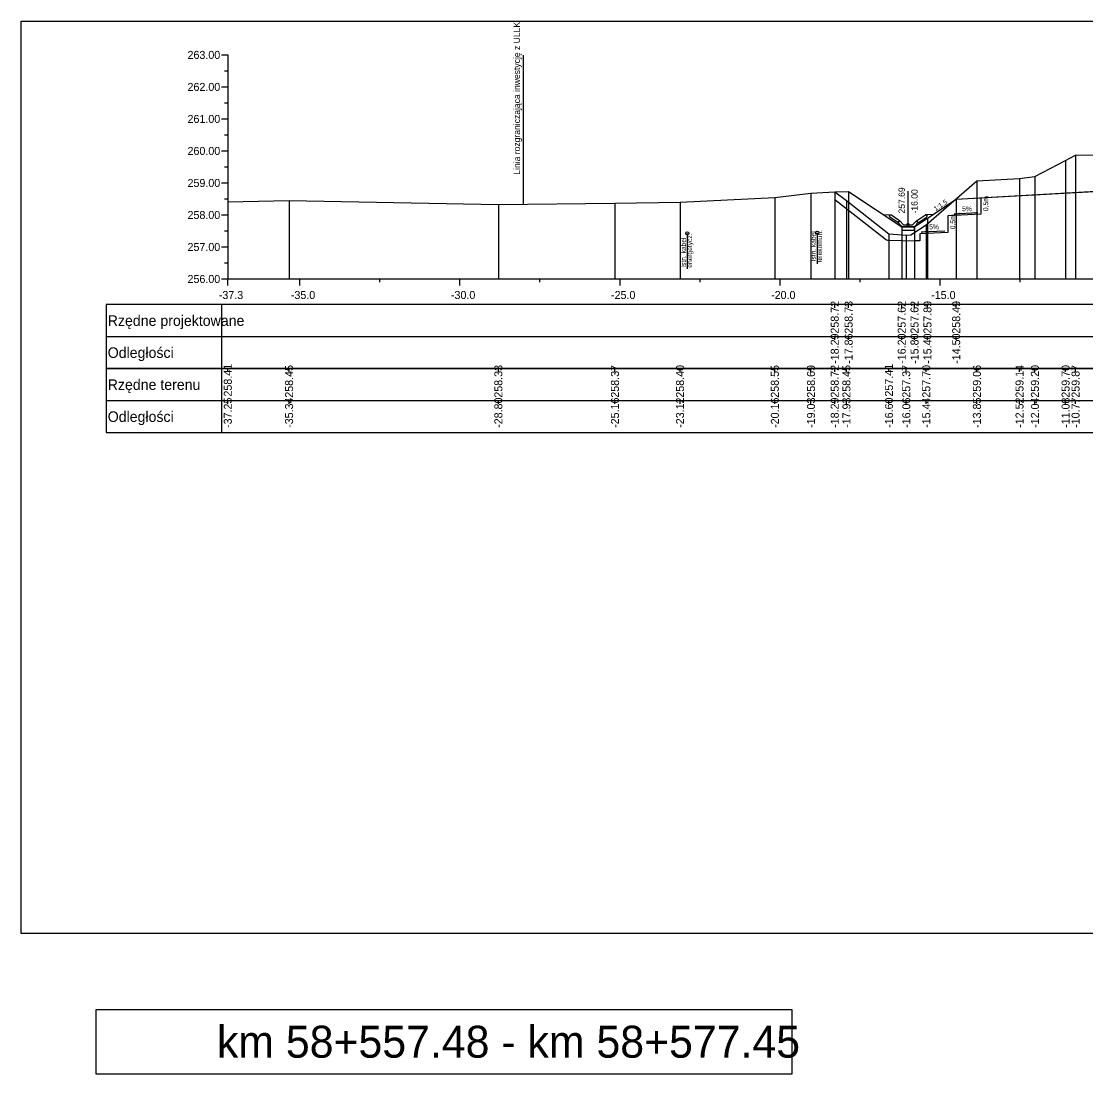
# Model space of a CAD drawing. Extents: x 6516023 to 6560129, y 5513077 to 5529206.
# Drawn here: x 6516634.51 to 6516667.76, y 5514513.78 to 5514546.66 of the extents above; entities that cross this region are included whole.
import ezdxf

# ---------------------------------------------------------------- set-up
doc = ezdxf.new("R2010")
doc.units = 0
for name, color, linetype in [('IR_default', 7, 'Continuous'), ('TOR_PRZEK_P-kable', 7, 'Continuous'), ('TOR_PRZEK_P-odwodnienie', 7, 'Continuous'), ('TOR_PRZEK_P-opisy', 7, 'Continuous'), ('TOR_PRZEK_P-pomoc', 7, 'Continuous'), ('TOR_PRZEK_P-schodkowanie+wymiana', 7, 'Continuous'), ('TOR_PRZEK_P-tabelka istniejace', 7, 'Continuous'), ('TOR_PRZEK_P-tabelka projektowane', 7, 'Continuous'), ('TOR_PRZEK_P-teren istniejacy', 7, 'Continuous'), ('TOR_PRZEK_P-uklad odniesienia', 7, 'Continuous'), ('TOR_PRZEK_P-warstwa ochronna II', 7, 'Continuous'), ('TOR_PS_T-granica PKP-projektowana', 7, 'Continuous'), ('TOR_PS_T-skarpy projektowane', 7, 'Continuous'), ('TOR_RAMKI-ramka+tabelka 1', 7, 'Continuous')]:
    doc.layers.add(name, color=color, linetype=linetype)

msp = doc.modelspace()

# ---------------------------------------------------------------- linework, layer by layer
at = {"layer": 'IR_default'}
msp.add_lwpolyline([(6516659.919, 5514541.328), (6516660.353, 5514541.336), (6516662.012, 5514540.231), (6516662.104, 5514540.231), (6516662.412, 5514540.231), (6516662.505, 5514540.293), (6516662.817, 5514540.501), (6516663.025, 5514540.64), (6516663.713, 5514541.098), (6516668.018, 5514541.344)], dxfattribs=at)
at = {"layer": 'TOR_PRZEK_P-kable'}
for p, q in [((6516655.315, 5514540.031), (6516655.315, 5514538.921)), ((6516659.373, 5514540.05), (6516659.373, 5514539.076))]:
    msp.add_line(p, q, dxfattribs=at)
for centre in [(6516655.315, 5514540.031), (6516659.373, 5514540.05)]:
    msp.add_circle(centre, 0.05, dxfattribs=at)
at = {"layer": 'TOR_PRZEK_P-odwodnienie'}
for p, q in [((6516662.212, 5514540.301), (6516662.212, 5514541.345)), ((6516661.903, 5514540.36), (6516661.641, 5514540.534)), ((6516661.947, 5514540.426), (6516661.667, 5514540.613)), ((6516662.476, 5514540.426), (6516662.757, 5514540.613)), ((6516662.521, 5514540.36), (6516662.782, 5514540.534)), ((6516661.914, 5514540.377), (6516661.903, 5514540.36)), ((6516661.904, 5514540.396), (6516661.952, 5514540.42)), ((6516661.947, 5514540.426), (6516661.939, 5514540.414)), ((6516662.072, 5514540.301), (6516661.952, 5514540.42)), ((6516662.022, 5514540.231), (6516662.402, 5514540.231)), ((6516662.072, 5514540.301), (6516662.352, 5514540.301)), ((6516662.352, 5514540.301), (6516662.472, 5514540.42)), ((6516662.472, 5514540.42), (6516662.519, 5514540.396)), ((6516662.476, 5514540.426), (6516662.485, 5514540.414)), ((6516662.51, 5514540.377), (6516662.521, 5514540.36))]:
    msp.add_line(p, q, dxfattribs=at)
for points in [[(6516661.42, 5514540.625), (6516661.667, 5514540.613)], [(6516661.617, 5514540.587), (6516661.667, 5514540.613)], [(6516661.617, 5514540.587), (6516661.641, 5514540.534)], [(6516663.003, 5514540.625), (6516662.757, 5514540.613)], [(6516662.807, 5514540.587), (6516662.757, 5514540.613)], [(6516662.807, 5514540.587), (6516662.782, 5514540.534)], [(6516661.939, 5514540.414), (6516661.904, 5514540.395)], [(6516661.952, 5514540.301), (6516661.904, 5514540.396)], [(6516661.904, 5514540.395), (6516661.914, 5514540.377)], [(6516662.022, 5514540.231), (6516661.952, 5514540.301)], [(6516662.012, 5514540.231), (6516662.011, 5514540.231), (6516662.012, 5514540.231), (6516662.011, 5514540.23), (6516662.012, 5514540.231), (6516662.012, 5514540.23), (6516662.012, 5514540.231), (6516662.012, 5514540.231)], [(6516662.412, 5514540.231), (6516662.012, 5514540.231), (6516662.012, 5514540.131), (6516662.412, 5514540.131), (6516662.412, 5514540.231)], [(6516662.402, 5514540.231), (6516662.472, 5514540.301)], [(6516662.412, 5514540.231), (6516662.411, 5514540.231), (6516662.412, 5514540.231), (6516662.411, 5514540.23), (6516662.412, 5514540.231), (6516662.412, 5514540.23), (6516662.412, 5514540.231), (6516662.412, 5514540.231)], [(6516662.472, 5514540.301), (6516662.519, 5514540.396)], [(6516662.485, 5514540.414), (6516662.52, 5514540.395)], [(6516662.52, 5514540.395), (6516662.51, 5514540.377)]]:
    msp.add_lwpolyline(points, dxfattribs=at)
msp.add_circle((6516662.212, 5514540.301), 0.035, dxfattribs=at)
at = {"layer": 'TOR_PRZEK_P-pomoc'}
msp.add_lwpolyline([(6516658.587, 5514515.781), (6516636.837, 5514515.781), (6516636.837, 5514513.781), (6516658.587, 5514513.781)], close=True, dxfattribs=at)
at = {"layer": 'TOR_PRZEK_P-schodkowanie+wymiana'}
for p, q in [((6516664.479, 5514541.142), (6516664.479, 5514540.627)), ((6516664.479, 5514540.627), (6516663.449, 5514540.576)), ((6516663.449, 5514540.576), (6516663.449, 5514540.061)), ((6516661.598, 5514539.815), (6516662.412, 5514539.798))]:
    msp.add_line(p, q, dxfattribs=at)
for points in [[(6516659.919, 5514541.086), (6516661.49, 5514539.857)], [(6516663.449, 5514540.061), (6516662.573, 5514540.017), (6516662.573, 5514539.798), (6516662.412, 5514539.798)]]:
    msp.add_lwpolyline(points, dxfattribs=at)
msp.add_arc((6516661.613, 5514540.014), 0.2, 231.9586, 265.5776, dxfattribs=at)
at = {"layer": 'TOR_PRZEK_P-tabelka istniejace'}
for p, q in [((6516637.163, 5514535.806), (6516637.163, 5514533.806)), ((6516640.763, 5514535.806), (6516640.763, 5514533.806)), ((6516640.963, 5514535.706), (6516640.963, 5514535.806)), ((6516642.877, 5514535.706), (6516642.877, 5514535.806)), ((6516649.414, 5514535.706), (6516649.414, 5514535.806)), ((6516653.055, 5514535.706), (6516653.055, 5514535.806)), ((6516655.088, 5514535.706), (6516655.088, 5514535.806)), ((6516658.049, 5514535.706), (6516658.049, 5514535.806)), ((6516659.178, 5514535.706), (6516659.178, 5514535.806)), ((6516659.919, 5514535.706), (6516659.919, 5514535.806)), ((6516660.285, 5514535.706), (6516660.285, 5514535.806)), ((6516661.613, 5514535.706), (6516661.613, 5514535.806)), ((6516662.155, 5514535.706), (6516662.155, 5514535.806)), ((6516662.778, 5514535.706), (6516662.778, 5514535.806)), ((6516664.36, 5514535.706), (6516664.36, 5514535.806)), ((6516665.691, 5514535.706), (6516665.691, 5514535.806)), ((6516666.172, 5514535.706), (6516666.172, 5514535.806)), ((6516667.13, 5514535.706), (6516667.13, 5514535.806)), ((6516667.442, 5514535.706), (6516667.442, 5514535.806)), ((6516637.163, 5514534.806), (6516720.963, 5514534.806)), ((6516640.963, 5514534.706), (6516640.963, 5514534.806)), ((6516642.877, 5514534.706), (6516642.877, 5514534.806)), ((6516649.414, 5514534.706), (6516649.414, 5514534.806)), ((6516653.055, 5514534.706), (6516653.055, 5514534.806)), ((6516655.088, 5514534.706), (6516655.088, 5514534.806)), ((6516658.049, 5514534.706), (6516658.049, 5514534.806)), ((6516659.178, 5514534.706), (6516659.178, 5514534.806)), ((6516659.919, 5514534.706), (6516659.919, 5514534.806)), ((6516660.285, 5514534.706), (6516660.285, 5514534.806)), ((6516661.613, 5514534.706), (6516661.613, 5514534.806)), ((6516662.155, 5514534.706), (6516662.155, 5514534.806)), ((6516662.778, 5514534.706), (6516662.778, 5514534.806)), ((6516664.36, 5514534.706), (6516664.36, 5514534.806)), ((6516665.691, 5514534.706), (6516665.691, 5514534.806)), ((6516666.172, 5514534.706), (6516666.172, 5514534.806)), ((6516667.13, 5514534.706), (6516667.13, 5514534.806)), ((6516667.442, 5514534.706), (6516667.442, 5514534.806))]:
    msp.add_line(p, q, dxfattribs=at)
for points in [[(6516667.442, 5514542.471), (6516667.442, 5514538.806), (6516667.442, 5514538.676), (6516667.442, 5514538.606)], [(6516667.13, 5514542.31), (6516667.13, 5514538.806), (6516667.13, 5514538.676), (6516667.13, 5514538.606)], [(6516666.172, 5514541.809), (6516666.172, 5514538.806), (6516666.172, 5514538.676), (6516666.172, 5514538.606)], [(6516664.36, 5514541.668), (6516664.36, 5514538.806), (6516664.36, 5514538.676), (6516664.36, 5514538.606)], [(6516665.691, 5514541.743), (6516665.691, 5514538.806), (6516665.691, 5514538.676), (6516665.691, 5514538.606)], [(6516658.049, 5514541.154), (6516658.049, 5514538.806), (6516658.049, 5514538.676), (6516658.049, 5514538.606)], [(6516659.178, 5514541.292), (6516659.178, 5514538.806), (6516659.178, 5514538.676), (6516659.178, 5514538.606)], [(6516659.919, 5514541.328), (6516659.919, 5514538.806), (6516659.919, 5514538.676), (6516659.919, 5514538.606)], [(6516640.963, 5514541.019), (6516640.963, 5514538.806), (6516640.963, 5514538.676), (6516640.963, 5514538.606)], [(6516642.877, 5514541.054), (6516642.877, 5514538.806), (6516642.877, 5514538.676), (6516642.877, 5514538.606)], [(6516649.414, 5514540.935), (6516649.414, 5514538.806), (6516649.414, 5514538.676), (6516649.414, 5514538.606)], [(6516653.055, 5514540.973), (6516653.055, 5514538.806), (6516653.055, 5514538.676), (6516653.055, 5514538.606)], [(6516655.088, 5514541.007), (6516655.088, 5514538.806), (6516655.088, 5514538.676), (6516655.088, 5514538.606)], [(6516660.285, 5514541.053), (6516660.285, 5514538.806), (6516660.285, 5514538.676), (6516660.285, 5514538.606)], [(6516662.778, 5514540.303), (6516662.778, 5514538.806), (6516662.778, 5514538.676), (6516662.778, 5514538.606)], [(6516661.613, 5514540.014), (6516661.613, 5514538.806), (6516661.613, 5514538.676), (6516661.613, 5514538.606)], [(6516662.155, 5514539.972), (6516662.155, 5514538.806), (6516662.155, 5514538.676), (6516662.155, 5514538.606)]]:
    msp.add_lwpolyline(points, dxfattribs=at)
msp.add_lwpolyline([(6516637.163, 5514535.806), (6516637.163, 5514533.806), (6516720.963, 5514533.806), (6516720.963, 5514535.806)], close=True, dxfattribs=at)
at = {"layer": 'TOR_PRZEK_P-tabelka projektowane'}
for p, q in [((6516637.163, 5514537.806), (6516637.163, 5514535.806)), ((6516640.763, 5514537.806), (6516640.763, 5514535.806)), ((6516659.919, 5514537.706), (6516659.919, 5514537.806)), ((6516660.353, 5514537.706), (6516660.353, 5514537.806)), ((6516662.012, 5514537.706), (6516662.012, 5514537.806)), ((6516662.412, 5514537.706), (6516662.412, 5514537.806)), ((6516662.817, 5514537.706), (6516662.817, 5514537.806)), ((6516663.713, 5514537.706), (6516663.713, 5514537.806)), ((6516637.163, 5514536.806), (6516720.963, 5514536.806)), ((6516659.919, 5514536.706), (6516659.919, 5514536.806)), ((6516660.353, 5514536.706), (6516660.353, 5514536.806)), ((6516662.012, 5514536.706), (6516662.012, 5514536.806)), ((6516662.412, 5514536.706), (6516662.412, 5514536.806)), ((6516662.817, 5514536.706), (6516662.817, 5514536.806)), ((6516663.713, 5514536.706), (6516663.713, 5514536.806))]:
    msp.add_line(p, q, dxfattribs=at)
for points in [[(6516659.919, 5514541.328), (6516659.919, 5514538.806), (6516659.919, 5514538.676), (6516659.919, 5514538.606)], [(6516660.353, 5514541.336), (6516660.353, 5514538.806), (6516660.353, 5514538.676), (6516660.353, 5514538.606)], [(6516663.713, 5514541.098), (6516663.713, 5514538.806), (6516663.713, 5514538.676), (6516663.713, 5514538.606)], [(6516662.817, 5514540.501), (6516662.817, 5514538.806), (6516662.817, 5514538.676), (6516662.817, 5514538.606)], [(6516662.012, 5514540.231), (6516662.012, 5514538.806), (6516662.012, 5514538.676), (6516662.012, 5514538.606)], [(6516662.412, 5514540.231), (6516662.412, 5514538.806), (6516662.412, 5514538.676), (6516662.412, 5514538.606)]]:
    msp.add_lwpolyline(points, dxfattribs=at)
msp.add_lwpolyline([(6516637.163, 5514537.806), (6516637.163, 5514535.806), (6516720.963, 5514535.806), (6516720.963, 5514537.806)], close=True, dxfattribs=at)
at = {"layer": 'TOR_PRZEK_P-teren istniejacy'}
msp.add_lwpolyline([(6516640.963, 5514541.019), (6516642.877, 5514541.054), (6516649.414, 5514540.935), (6516653.055, 5514540.973), (6516655.088, 5514541.007), (6516658.049, 5514541.154), (6516659.178, 5514541.292), (6516659.919, 5514541.328), (6516660.285, 5514541.053), (6516661.613, 5514540.014), (6516662.155, 5514539.972), (6516662.295, 5514539.983), (6516662.778, 5514540.303), (6516664.36, 5514541.668), (6516665.691, 5514541.743), (6516666.172, 5514541.809), (6516667.13, 5514542.31), (6516667.442, 5514542.471), (6516669.853, 5514542.48)], dxfattribs=at)
at = {"layer": 'TOR_PRZEK_P-uklad odniesienia'}
for p, q in [((6516640.763, 5514545.606), (6516640.963, 5514545.606)), ((6516640.963, 5514545.606), (6516640.963, 5514538.606)), ((6516640.863, 5514545.106), (6516640.963, 5514545.106)), ((6516640.763, 5514544.606), (6516640.963, 5514544.606)), ((6516640.863, 5514544.106), (6516640.963, 5514544.106)), ((6516640.763, 5514543.606), (6516640.963, 5514543.606)), ((6516640.863, 5514543.106), (6516640.963, 5514543.106)), ((6516640.763, 5514542.606), (6516640.963, 5514542.606)), ((6516640.863, 5514542.106), (6516640.963, 5514542.106)), ((6516640.763, 5514541.606), (6516640.963, 5514541.606)), ((6516640.863, 5514541.106), (6516640.963, 5514541.106)), ((6516640.763, 5514540.606), (6516640.963, 5514540.606)), ((6516640.863, 5514540.106), (6516640.963, 5514540.106)), ((6516640.763, 5514539.606), (6516640.963, 5514539.606)), ((6516640.863, 5514539.106), (6516640.963, 5514539.106)), ((6516640.763, 5514538.606), (6516640.963, 5514538.606)), ((6516640.963, 5514538.606), (6516720.963, 5514538.606)), ((6516640.963, 5514538.506), (6516640.963, 5514538.606)), ((6516640.963, 5514538.406), (6516640.963, 5514538.606)), ((6516643.213, 5514538.406), (6516643.213, 5514538.606)), ((6516645.713, 5514538.506), (6516645.713, 5514538.606)), ((6516648.213, 5514538.406), (6516648.213, 5514538.606)), ((6516650.713, 5514538.506), (6516650.713, 5514538.606)), ((6516653.213, 5514538.406), (6516653.213, 5514538.606)), ((6516655.713, 5514538.506), (6516655.713, 5514538.606)), ((6516658.213, 5514538.406), (6516658.213, 5514538.606)), ((6516660.713, 5514538.506), (6516660.713, 5514538.606)), ((6516663.213, 5514538.406), (6516663.213, 5514538.606)), ((6516665.713, 5514538.506), (6516665.713, 5514538.606))]:
    msp.add_line(p, q, dxfattribs=at)
at = {"layer": 'TOR_PRZEK_P-warstwa ochronna II'}
msp.add_lwpolyline([(6516659.919, 5514541.328), (6516660.353, 5514541.336), (6516662.012, 5514540.231), (6516662.412, 5514540.231), (6516662.817, 5514540.501), (6516663.713, 5514541.098), (6516669.534, 5514541.431), (6516670.013, 5514541.75), (6516670.591, 5514541.773), (6516678.963, 5514542.108), (6516680.238, 5514542.159), (6516681.513, 5514542.109), (6516689.407, 5514541.793), (6516690.013, 5514541.768), (6516690.492, 5514541.449), (6516692.313, 5514541.276), (6516693.441, 5514540.524), (6516693.921, 5514540.204), (6516694.321, 5514540.204), (6516695.526, 5514541.008)], dxfattribs=at)
at = {"layer": 'TOR_PS_T-granica PKP-projektowana'}
msp.add_line((6516650.204, 5514540.943), (6516650.204, 5514545.6), dxfattribs=at)
at = {"layer": 'TOR_PS_T-skarpy projektowane'}
for points in [[(6516664.386, 5514540.672), (6516663.651, 5514540.632), (6516663.823, 5514540.663)], [(6516663.356, 5514540.105), (6516662.621, 5514540.065), (6516662.793, 5514540.096)]]:
    msp.add_lwpolyline(points, dxfattribs=at)
at = {"layer": 'TOR_RAMKI-ramka+tabelka 1'}
msp.add_lwpolyline([(6516634.513, 5514546.656), (6516882.013, 5514546.656), (6516882.013, 5514518.156), (6516634.513, 5514518.156)], close=True, dxfattribs=at)

# ---------------------------------------------------------------- texts
at = {"layer": 'TOR_PRZEK_P-kable'}
for s, height, p in [('Istn. kabel', 0.14999, (6516655.27, 5514538.957)), ('energetycz.', 0.14999, (6516655.464, 5514538.957)), ('Istn. kabel', 0.14999, (6516659.328, 5514539.152)), ('telekomun.', 0.15, (6516659.522, 5514539.124))]:
    msp.add_text(s, height=height, rotation=90.0511, dxfattribs=at).set_placement(p)
at = {"layer": 'TOR_PRZEK_P-odwodnienie'}
for s, p in [('257.69', (6516662.112, 5514540.651)), ('-16.00', (6516662.512, 5514540.651))]:
    msp.add_text(s, height=0.2, rotation=90, dxfattribs=at).set_placement(p)
at = {"layer": 'TOR_PRZEK_P-opisy'}
msp.add_text('1:1,5', height=0.15, rotation=34.0701, dxfattribs=at).set_placement((6516663.076, 5514540.718))
at = {"layer": 'TOR_PRZEK_P-pomoc'}
msp.add_text('km 58+557.48 - km 58+577.45', height=1, dxfattribs=at).set_placement((6516640.623, 5514514.281))
at = {"layer": 'TOR_PRZEK_P-schodkowanie+wymiana'}
for p in [(6516664.714, 5514540.723), (6516663.684, 5514540.157)]:
    msp.add_text('0,5m', height=0.1545, rotation=90, dxfattribs=at).set_placement(p)
at = {"layer": 'TOR_PRZEK_P-tabelka istniejace'}
for s, p in [('258.41', (6516641.088, 5514534.933)), ('258.45', (6516643.002, 5514534.897)), ('258.33', (6516649.539, 5514534.898)), ('258.37', (6516653.18, 5514534.898)), ('258.40', (6516655.213, 5514534.898)), ('258.55', (6516658.174, 5514534.897)), ('258.69', (6516659.303, 5514534.898)), ('258.72', (6516660.044, 5514534.9)), ('258.45', (6516660.41, 5514534.897)), ('257.41', (6516661.738, 5514534.933)), ('257.37', (6516662.28, 5514534.898)), ('257.70', (6516662.903, 5514534.898)), ('259.06', (6516664.485, 5514534.898)), ('259.14', (6516665.816, 5514534.899)), ('259.20', (6516666.297, 5514534.898)), ('259.70', (6516667.255, 5514534.898)), ('259.87', (6516667.567, 5514534.898)), ('-37.25', (6516641.088, 5514533.953)), ('-35.34', (6516643.002, 5514533.955)), ('-28.80', (6516649.539, 5514533.955)), ('-25.16', (6516653.18, 5514533.954)), ('-23.12', (6516655.213, 5514533.956)), ('-20.16', (6516658.174, 5514533.954)), ('-19.03', (6516659.303, 5514533.954)), ('-18.29', (6516660.044, 5514533.955)), ('-17.93', (6516660.41, 5514533.954)), ('-16.60', (6516661.738, 5514533.955)), ('-16.06', (6516662.28, 5514533.954)), ('-15.44', (6516662.903, 5514533.955)), ('-13.85', (6516664.485, 5514533.953)), ('-12.52', (6516665.816, 5514533.956)), ('-12.04', (6516666.297, 5514533.955)), ('-11.08', (6516667.255, 5514533.954)), ('-10.77', (6516667.567, 5514533.955))]:
    msp.add_text(s, height=0.25, rotation=90, dxfattribs=at).set_placement(p)
for s, p in [('Rzędne terenu', (6516637.213, 5514535.141)), ('Odległości', (6516637.213, 5514534.141))]:
    msp.add_text(s, height=0.33, dxfattribs=at).set_placement(p)
at = {"layer": 'TOR_PRZEK_P-tabelka projektowane'}
for s, p in [('258.72', (6516660.044, 5514536.9)), ('258.73', (6516660.478, 5514536.898)), ('257.62', (6516662.137, 5514536.9)), ('257.62', (6516662.537, 5514536.9)), ('257.89', (6516662.942, 5514536.898)), ('258.49', (6516663.838, 5514536.898)), ('-18.29', (6516660.044, 5514535.955)), ('-17.86', (6516660.478, 5514535.954)), ('-16.20', (6516662.137, 5514535.955)), ('-15.80', (6516662.537, 5514535.955)), ('-15.40', (6516662.942, 5514535.955)), ('-14.50', (6516663.838, 5514535.955))]:
    msp.add_text(s, height=0.25, rotation=90, dxfattribs=at).set_placement(p)
for s, p in [('Rzędne projektowane', (6516637.213, 5514537.141)), ('Odległości', (6516637.213, 5514536.141))]:
    msp.add_text(s, height=0.33, dxfattribs=at).set_placement(p)
at = {"layer": 'TOR_PRZEK_P-uklad odniesienia'}
for s, height, p in [('263.00', 0.25, (6516639.705, 5514545.481)), ('262.00', 0.25, (6516639.705, 5514544.481)), ('261.00', 0.25, (6516639.705, 5514543.481)), ('260.00', 0.25, (6516639.705, 5514542.481)), ('259.00', 0.25, (6516639.705, 5514541.481)), ('258.00', 0.25, (6516639.705, 5514540.481)), ('257.00', 0.25, (6516639.705, 5514539.481)), ('256.00', 0.25, (6516639.705, 5514538.481)), ('-', 0.0001, (6516640.963, 5514538.606)), ('-37.3', 0.25, (6516640.682, 5514537.981)), ('-35.0', 0.25, (6516642.932, 5514537.981)), ('-30.0', 0.25, (6516647.932, 5514537.981)), ('-25.0', 0.25, (6516652.932, 5514537.981)), ('-20.0', 0.25, (6516657.932, 5514537.981)), ('-15.0', 0.25, (6516662.932, 5514537.981))]:
    msp.add_text(s, height=height, dxfattribs=at).set_placement(p)
at = {"layer": 'TOR_PS_T-granica PKP-projektowana'}
msp.add_text('Linia rozgraniczająca inwestycję z ULLK', height=0.2, rotation=90.0511, dxfattribs=at).set_placement((6516650.093, 5514541.864))
at = {"layer": 'TOR_PS_T-skarpy projektowane'}
for p in [(6516663.897, 5514540.723), (6516662.867, 5514540.157)]:
    msp.add_text('5%', height=0.1545, dxfattribs=at).set_placement(p)

doc.saveas('drawing.dxf')
